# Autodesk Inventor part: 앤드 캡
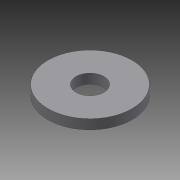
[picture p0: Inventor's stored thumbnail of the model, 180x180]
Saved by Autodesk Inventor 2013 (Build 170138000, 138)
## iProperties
Created: 2024-02
Part Number: 앤드 캡
Material: 강철, 연강
Document SubType Name: Modeling
Designer: mdu-01
Density: 7.86 g/cm^3
Mass: 5.06089 g
Surface Area: 7.52097 cm^2
Volume: 0.643879 cm^3
Author: mdu-01
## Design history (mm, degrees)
sketch "스케치1"
  geometry: L1 (-0.3, -2.5)-(-0.3, 2.5) reference; C1 r 10 at (8.5, 0); C2 r 3.3 at (8.5, 0); A1 r 6.5 centre (8.5, 0) between (2.5, -2.5) and (2.5, 2.5) reference; 1 further point
  constraints: 2 centre point, 2 coincident
  dimensions: "d0" = 20 diameter of C1; "d1" = 6.6 diameter of C2
extrude "돌출1" new body sketch "스케치1" distance "d2" = 2.3; taper "d3" = 0 deg
node "솔리드1"
node "참조1"
node "참조2"
